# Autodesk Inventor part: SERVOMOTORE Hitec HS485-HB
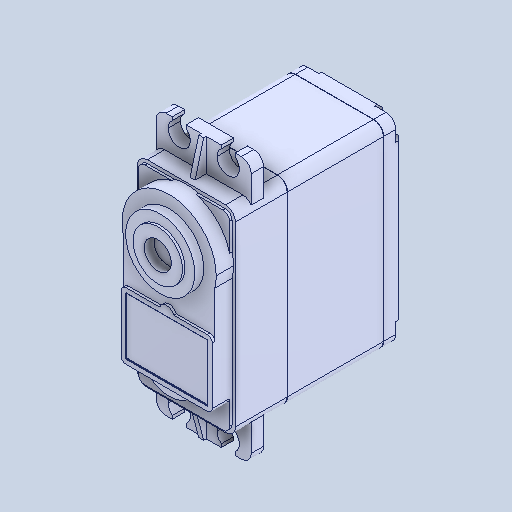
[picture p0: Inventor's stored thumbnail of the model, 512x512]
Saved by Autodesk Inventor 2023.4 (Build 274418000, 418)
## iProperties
Created: 2023-11
Part Number: SERVOMOTORE Hitec HS485-HB
Material: Générique
Document SubType Name: Modeling
Designer: mel
Density: 1 g/cm^3
Appearance: Par défaut
Author: mel
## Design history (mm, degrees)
feature "Base1"
feature "Base2"
feature "Base3"
feature "Base4"
node "Solide1"
node "Solide2"
node "Solide3"
node "Solide4"
